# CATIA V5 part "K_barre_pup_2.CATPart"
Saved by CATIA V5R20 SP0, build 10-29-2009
Part number: barre_pup_2
Bounding box of the stored display mesh (mm): x -69.855 to -43.832, y 186.148 to 191.148, z -108.142 to 95.446
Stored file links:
  G:\Khaled_CFAO_2011\ST2M\ST2M_GR2\gcausse\Khaled\CAD_ThinkMotion\K_barre_pup_2.CATPart
  C:\Documents and Settings\gcausse\Bureau\video thinkmotio\assemblage_gcausse\pupitre_think.CATProduct
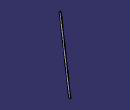
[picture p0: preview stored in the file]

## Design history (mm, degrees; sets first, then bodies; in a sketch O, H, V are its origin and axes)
Set1
  Sketch1 on Plane1, origin (-54.7303, 0, 6.7329), H (0, 1, 0), V (0.1221, 0, 0.9925)
    line L1 (191.1479, 86.7587) -> (191.1479, -113.2413)
    arc A1 centre (188.6479, -113.2413) radius 2.5 from (191.1479, -113.2413) to (186.1479, -113.2413) cw
    point P3 (188.6479, -113.2413)
    line L2 (186.1479, -113.2413) -> (186.1479, 86.7587)
    arc A2 centre (188.6479, 86.7587) radius 2.5 from (186.1479, 86.7587) to (191.1479, 86.7587) cw
    point P6 (188.6479, 86.7587)
    reference projected point E1 (188.6479, 86.7587) from Point1
    reference projected point E2 (188.6479, -113.2413) from Point2
    reference projected line E3 (188.6479, 86.7587) -> (188.6479, -113.2413) from Line1
    reference projected line E4 (188.6479, 86.7587) -> (188.6479, -113.2413) from Line1
    distance L1 L2 = 5
    tangency: A1 L1, L2 A1, A2 L1, A2 L2
    coincidence: P6 E1, P3 E2
    parallelism: L1 E3, E4 L2
Set2
  Plane1: linked copy from another document
  Point1: linked copy from another document
  Point2: linked copy from another document
  Line1: linked copy from another document
Body1 (main body)
  Pad1: profile Sketch1, direction (0.9925, 0, -0.1221), length -1
  Sketch2 on start face of Pad1, origin (-55.4185, 187.1085, 1.1388), H (0.1221, 0, 0.9925), V (0, -1, 0)
    point P1 (92.3949, -1.5395)
    reference projected point E1 (92.3949, -1.5395) from Point1
    coincidence: P1 E1
  Hole1: placed by Sketch2, at (-44.1372, 188.6479, 92.8425) direction (-0.9925, 0, 0.1221), diameter 1, depth 1
  Sketch3 on start face of Pad1, origin (-51.6106, 189.747, 32.0925), H (0.1221, 0, 0.9925), V (0, -1, 0)
    point P1 (-138.7921, 1.099)
    reference projected point E1 (-138.7921, 1.099) from Point2
    coincidence: P1 E1
  Hole2: placed by Sketch3, at (-68.557, 188.6479, -105.6611) direction (-0.9925, 0, 0.1221), diameter 1, depth 1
